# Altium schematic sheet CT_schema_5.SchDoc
size 278 x 170 mm
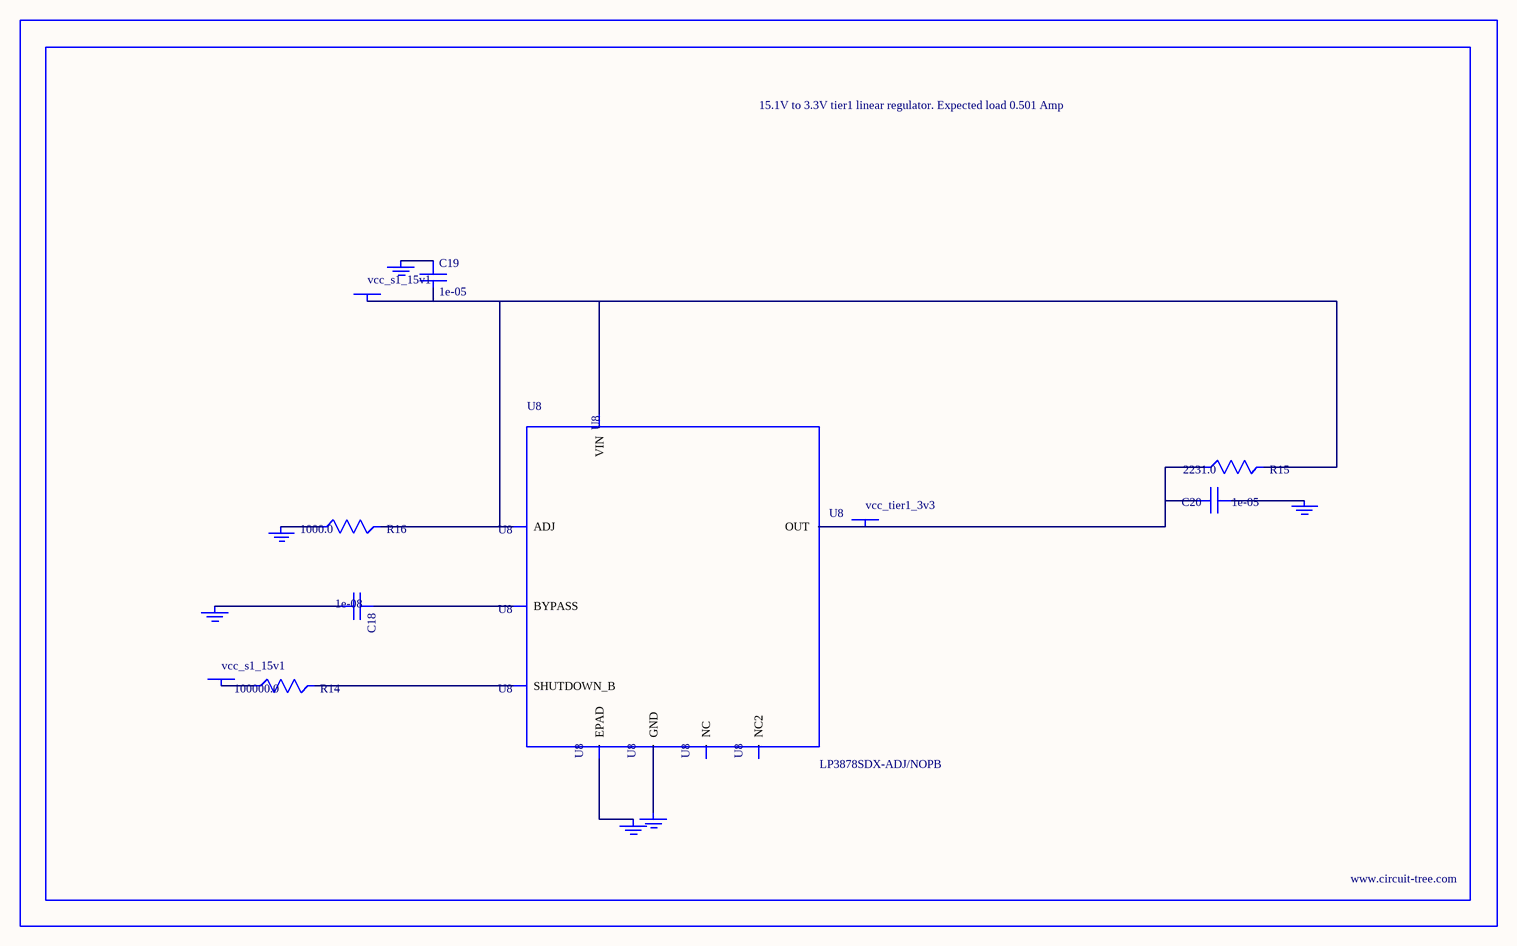
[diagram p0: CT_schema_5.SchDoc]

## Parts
BORDER4  (no value)
C18  1e-08  [C0402]
C19  1e-05  [C1210]
C20  1e-05  [C1210]
GND_INSTANCE_4_0  (no value)
GND_INSTANCE_4_1  (no value)
GND_INSTANCE_4_2  (no value)
GND_INSTANCE_4_3  (no value)
GND_INSTANCE_4_4  (no value)
GND_INSTANCE_4_5  (no value)
POWER_INSTANCE_4_0  vcc_s1_15v1
POWER_INSTANCE_4_1  vcc_s1_15v1
POWER_INSTANCE_4_2  vcc_tier1_3v3
R14  100000.0  [R0603]
R15  2231.0  [R0603]
R16  1000.0  [R0603]
U8  LP3878SDX-ADJ/NOPB  [WSON-8]

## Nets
NetC18_1: C18.1 U8.1(BYPASS)
NetC18_2: C18.2 GND_INSTANCE_4_0.0(GND)
NetC19_1: C19.1 GND_INSTANCE_4_1.0(GND)
NetC19_2: C19.2 POWER_INSTANCE_4_0.0(PWR) R15.2 R16.2 U8.4(VIN) U8.6(ADJ)
NetC20_1: C20.1 GND_INSTANCE_4_2.0(GND)
NetC20_2: C20.2 POWER_INSTANCE_4_2.0(PWR) R15.1 U8.5(OUT)
NetGND_INSTANCE_4_3_0: GND_INSTANCE_4_3.0(GND) R16.1
NetGND_INSTANCE_4_4_0: GND_INSTANCE_4_4.0(GND) U8.PAD(EPAD)
NetGND_INSTANCE_4_5_0: GND_INSTANCE_4_5.0(GND) U8.3(GND)
NetPOWER_INSTANCE_4_1_0: POWER_INSTANCE_4_1.0(PWR) R14.1
NetR14_2: R14.2 U8.8(SHUTDOWN_B)

Not connected (* = marked no-connect by the designer): U8 2(NC) 7(NC2)

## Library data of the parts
BORDER4 = BORDER_PAGE4
C18 = C0402C103K3RAC
C19 = C1210C106K5PACTU
C20 = GRM32DR61E106MA12L
GND_INSTANCE_4_0-GND_INSTANCE_4_5 = GND
POWER_INSTANCE_4_0-POWER_INSTANCE_4_2 = PWR
R14 = RC0603JR-07100KL
R15 = R15
R16 = RC0603JR-071KL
